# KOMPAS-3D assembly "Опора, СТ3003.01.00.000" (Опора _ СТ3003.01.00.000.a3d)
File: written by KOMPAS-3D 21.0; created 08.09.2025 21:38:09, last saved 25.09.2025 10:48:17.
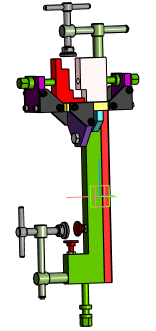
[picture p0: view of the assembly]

Document properties: Полное имя файла: C:\Users\1\Yandex.Disk\Документы\Новая папка\Стапель №2\Стапель _ СТ3003.00.00.000\Опора _ СТ3003.01.00.000\3D\Опора _ СТ3003.01.00.000.a3d

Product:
- Part/product: Опора  | designation СТ3003.01.00.000
    Масса: 16.700346
    Форматы листов документа: A3
  - Component [detail]: Винт  | designation СТ3003.01.00.001  | pos. 4  | Материал: Круг$d30 ГОСТ 2590-2006;Ст3сп ГОСТ 535-2005$ (density 7850 kg/m3); Масса: 0.303608; Форматы листов документа: A4; additional columns: 120; source file: ..\2D\Винт _ СТ3003.01.00.001.cdw, Винт _ СТ3003.01.00.001.m3d
  - Component [standard]: Винт с шестигранной головкой ГОСТ Р ИСО 4017-М16 x 45-5.8-A2P  | pos. 5  | Материал: Сталь (density 1000 kg/m3); Масса: 0.01392; Раздел спецификации: Стандартные изделия; Рассекать на разрезах: no; additional columns: ГОСТ Р ИСО 4017-2013; М16 x 45 - 5.8 - A2P
  - Component [assembly]: Струбцина  | designation СТ3003.01.03.000-01  | pos. 3  | Масса: 1.075052; Форматы листов документа: A3; source file: ..\2D\Струбцина _ СТ3003.01.03.000\Струбцина _ СТ3003.01.03.000.cdw, Струбцина _ СТ3003.01.03.000\Струбцина _ СТ3003.01.03.000.a3d
  - Component [assembly]: Струбцина  | designation СТ3003.01.03.000  | pos. 3  | Масса: 1.103282; Раздел спецификации: Сборочные единицы; Форматы листов документа: A3; source file: ..\2D\Струбцина _ СТ3003.01.03.000\Струбцина _ СТ3003.01.03.000.cdw, Струбцина _ СТ3003.01.03.000\Струбцина _ СТ3003.01.03.000.a3d
  - Component [assembly]: Кронштейн  | designation СТ3003.01.01.000  | pos. 1  | Масса: 9.381703; Форматы листов документа: A2; source file: ..\2D\Кронштейн _ СТ3003.01.01.000\Кронштейн _ СТ3003.01.01.000.cdw, Кронштейн _ СТ3003.01.01.000\Кронштейн _ СТ3003.01.01.000.a3d
  - Component [assembly]: Кронштейн  | designation СТ3003.01.02.000  | pos. 2  | Масса: 4.787723; Форматы листов документа: A3; source file: ..\2D\Кронштейн _ СТ3003.01.02.000\Кронштейн _ СТ3003.01.02.000.cdw, Кронштейн _ СТ3003.01.02.000\Кронштейн _ СТ3003.01.02.000.a3d

Referenced files in C:\Users\1\Yandex.Disk\Документы\Новая папка\Стапель №2\Стапель _ СТ3003.00.00.000\Опора _ СТ3003.01.00.000\3D\Кронштейн _ СТ3003.01.01.000\: Кронштейн _ СТ3003.01.01.000.a3d
Referenced files in C:\Users\1\Yandex.Disk\Документы\Новая папка\Стапель №2\Стапель _ СТ3003.00.00.000\Опора _ СТ3003.01.00.000\3D\Струбцина _ СТ3003.01.03.000\: Струбцина _ СТ3003.01.03.000.a3d
Referenced files in C:\Users\1\Yandex.Disk\Документы\Новая папка\Стапель №2\Стапель _ СТ3003.00.00.000\Опора _ СТ3003.01.00.000\3D\Кронштейн _ СТ3003.01.02.000\: Кронштейн _ СТ3003.01.02.000.a3d
Referenced files in C:\Users\1\Yandex.Disk\Документы\Новая папка\Стапель №2\Стапель _ СТ3003.00.00.000\Опора _ СТ3003.01.00.000\3D\: Винт _ СТ3003.01.00.001.m3d
Referenced files in C:\Users\1\Yandex.Disk\Документы\Новая папка\Стапель №2\Стапель _ СТ3003.00.00.000\Опора _ СТ3003.01.00.000\2D\Кронштейн _ СТ3003.01.01.000\: Кронштейн _ СТ3003.01.01.000.cdw
Referenced files in C:\Users\1\Yandex.Disk\Документы\Новая папка\Стапель №2\Стапель _ СТ3003.00.00.000\Опора _ СТ3003.01.00.000\2D\Струбцина _ СТ3003.01.03.000\: Струбцина _ СТ3003.01.03.000.cdw
Referenced files in C:\Users\1\Yandex.Disk\Документы\Новая папка\Стапель №2\Стапель _ СТ3003.00.00.000\Опора _ СТ3003.01.00.000\2D\Кронштейн _ СТ3003.01.02.000\: Кронштейн _ СТ3003.01.02.000.cdw
Referenced files in C:\Users\1\Yandex.Disk\Документы\Новая папка\Стапель №2\Стапель _ СТ3003.00.00.000\Опора _ СТ3003.01.00.000\2D\: Винт _ СТ3003.01.00.001.cdw
Referenced files in C:\Program Files\ASCON\KOMPAS-3D v21\Libs\PartLib\DATA\VAULT\Methods\Kompas\3D\: PLib_Bolt_1_ISO_1100.m3d
Referenced files in C:\Program Files\ASCON\KOMPAS-3D v21\Libs\PARTLib\DATA\vault\Methods\Kompas\3D\: PLib_Bolt_1_ISO_1100.m3d
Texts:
  СТ3003.01.01.000
  СТ3003.01.03.000 - 01
  СТ3003.01.03.000-01
  СТ3003.01.03.000
  СТ3003.01.02.000
  Винт с шестигранной головкой
  ГОСТ Р ИСО
  СТ3003.01.00.001
  Винт с шестигранной головкой ГОСТ Р ИСО 4017 - М16 x 45 - 5.8 - A2P
  СТ3003.01.00.000
  СТ3003.01.01.000 Кронштейн
  СТ3003.01.02.000 Кронштейн
  СТ3003.01.03.000 Струбцина
  СТ3003.01.03.000-01 Струбцина
  hole1
  hole2
  СТ3003.01.00.001 Винт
